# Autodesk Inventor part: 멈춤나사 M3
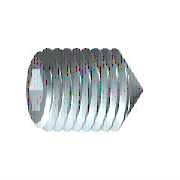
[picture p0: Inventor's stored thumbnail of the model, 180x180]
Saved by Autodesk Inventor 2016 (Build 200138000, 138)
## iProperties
Created: 2012-02
Part Number: 멈춤나사 M3
Material: 강철, 연강
Description: 6각 소켓 머리 없는 멈춤 나사
Document SubType Name: Modeling
Standard: KS B 1028
Designer: mduedu
Standards Organization: KS
Language: ko-KR
Size Designation: 원추점 M3x8
Categories: <MemberInstance><Categories><Category DisplayName="조임쇠" InternalName="e4da775c-781d-43d5-af7c-5136215cf5a6" Mnemonic="FSTN"><Category DisplayName="볼트" InternalN
Density: 7.86 g/cm^3
Mass: 0.360339 g
Surface Area: 0.888172 cm^2
Volume: 0.0458447 cm^3
Appearance: 강철
IsCustomPart: 1
Author: mduedu
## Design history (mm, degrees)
sketch "스케치1"
  geometry: L1 (0, 0)-(5.5, 0); L2 (8, 0.866)-(8, 1.5); L3 (8, 1.5)-(0, 1.5); L4 (8, 0.866)-(6, 0.866); L5 (6, 0.866)-(5.5, 0); L6 (0, -0.3)-(0, 1.8) reference; L7 (0, 1.5)-(0, 0)
  constraints: 13 end point, 3 parallel, 1 collinear, 1 perpendicular, 1 point on line
  dimensions: "d0" = 2 distance of L2.start L4.end (= INTI); "d1" = 60 deg angle of L5 L1; "d2" = 3 diameter of L3 L1 (= NND); "d3" = 1.73205 diameter of L4 L1 (= 1.1547 x SW); "d5" = 8 distance from line of L2 L3.end (= NLG)
revolve "본체" sketch "스케치1" stored, may be unused: angle "d6" = 90 deg
sketch "스케치2"
  geometry: L1 (-0.433, 0.75)-(0.433, 0.75); L2 (0.433, 0.75)-(0.866, 0); L3 (0.866, 0)-(0.433, -0.75); L4 (0.433, -0.75)-(-0.433, -0.75); L5 (-0.433, -0.75)-(-0.866, 0); L6 (-0.866, 0)-(-0.433, 0.75); 3 further points
  constraints: 12 end point, 1 coincident, 1 horizontal, 13 other
extrude "슬롯" join sketch "스케치2" taper "d7" = 0 deg; stored distance "d21" = 10
workaxis "Work Axis1"
workplane "Work Plane1"
sketch "스케치5"
  geometry: L1 (-4, -0.15)-(-2.65, -1.5) reference; L2 (-4, 0.15)-(-2.65, 1.5) reference; L3 (-2.65, 1.5)-(-4.15, 0); L4 (-2.65, -1.5)-(-4.15, 0); 1 further point
  constraints: 4 end point, 1 horizontal alignment, 1 perpendicular
node "작업점1"
body "Solid1"
feature "스레드" dims "d12" = 8 (= NLG), "d13" = 0
chamfer "모따기1" distance "d8" = 1.35 (computed from NND, SPD, FAWI); stored, may be unused: angle "d9" = 45 deg (= FAWI), second distance "d34" = 1.35 (computed from NND, SPD, FAWI)
chamfer "모따기2" distance "d10" = 0.30673 (= -0.5 x GD1 + 0.5 x NND); stored, may be unused: angle "d11" = 45 deg (= FAWI), second distance "d35" = 0.30673 (= -0.5 x GD1 + 0.5 x NND)
other parameters: "NND" = 3 [user parameter; used in 5 equation terms], "NLG" = 8 [user parameter; used in 2 equation terms], "INTI" = 2 [user parameter; used in 1 equation term], "FAWI" = 45 deg [user parameter; used in 4 equation terms], "SW" = 1.5 [user parameter; used in 2 equation terms], "GD1" = 2.38655 (= THREADDIA - 1.2269 x PTC) [user parameter; used in 2 equation terms], "d4" = 0, "FAWI1" = 45 deg [user parameter], "SPD" = 0.3 [user parameter; used in 2 equation terms], "d36" = 0, "d37" = 0, "GUL" = 0.30673 (= 0.61345 x PTC) [user parameter], "TOA" = 30 deg [user parameter], "THREADDIA" = 3 [user parameter; used in 1 equation term], "PTC" = 0.5 [user parameter; used in 4 equation terms], "GAL" = 0.30673 (= 0.61345 x PTC) [user parameter], "E0" = 1.7325 (= 1.155 x SW) [user parameter]
